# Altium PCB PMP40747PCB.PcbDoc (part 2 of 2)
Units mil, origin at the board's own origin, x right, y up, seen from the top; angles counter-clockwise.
Board outline 2952.76 x 3937.01 mil, 2 copper layers (Top Layer, Bottom Layer), stack 62 mil thick; 109 components, 53 nets, 257 pads, 138 vias.
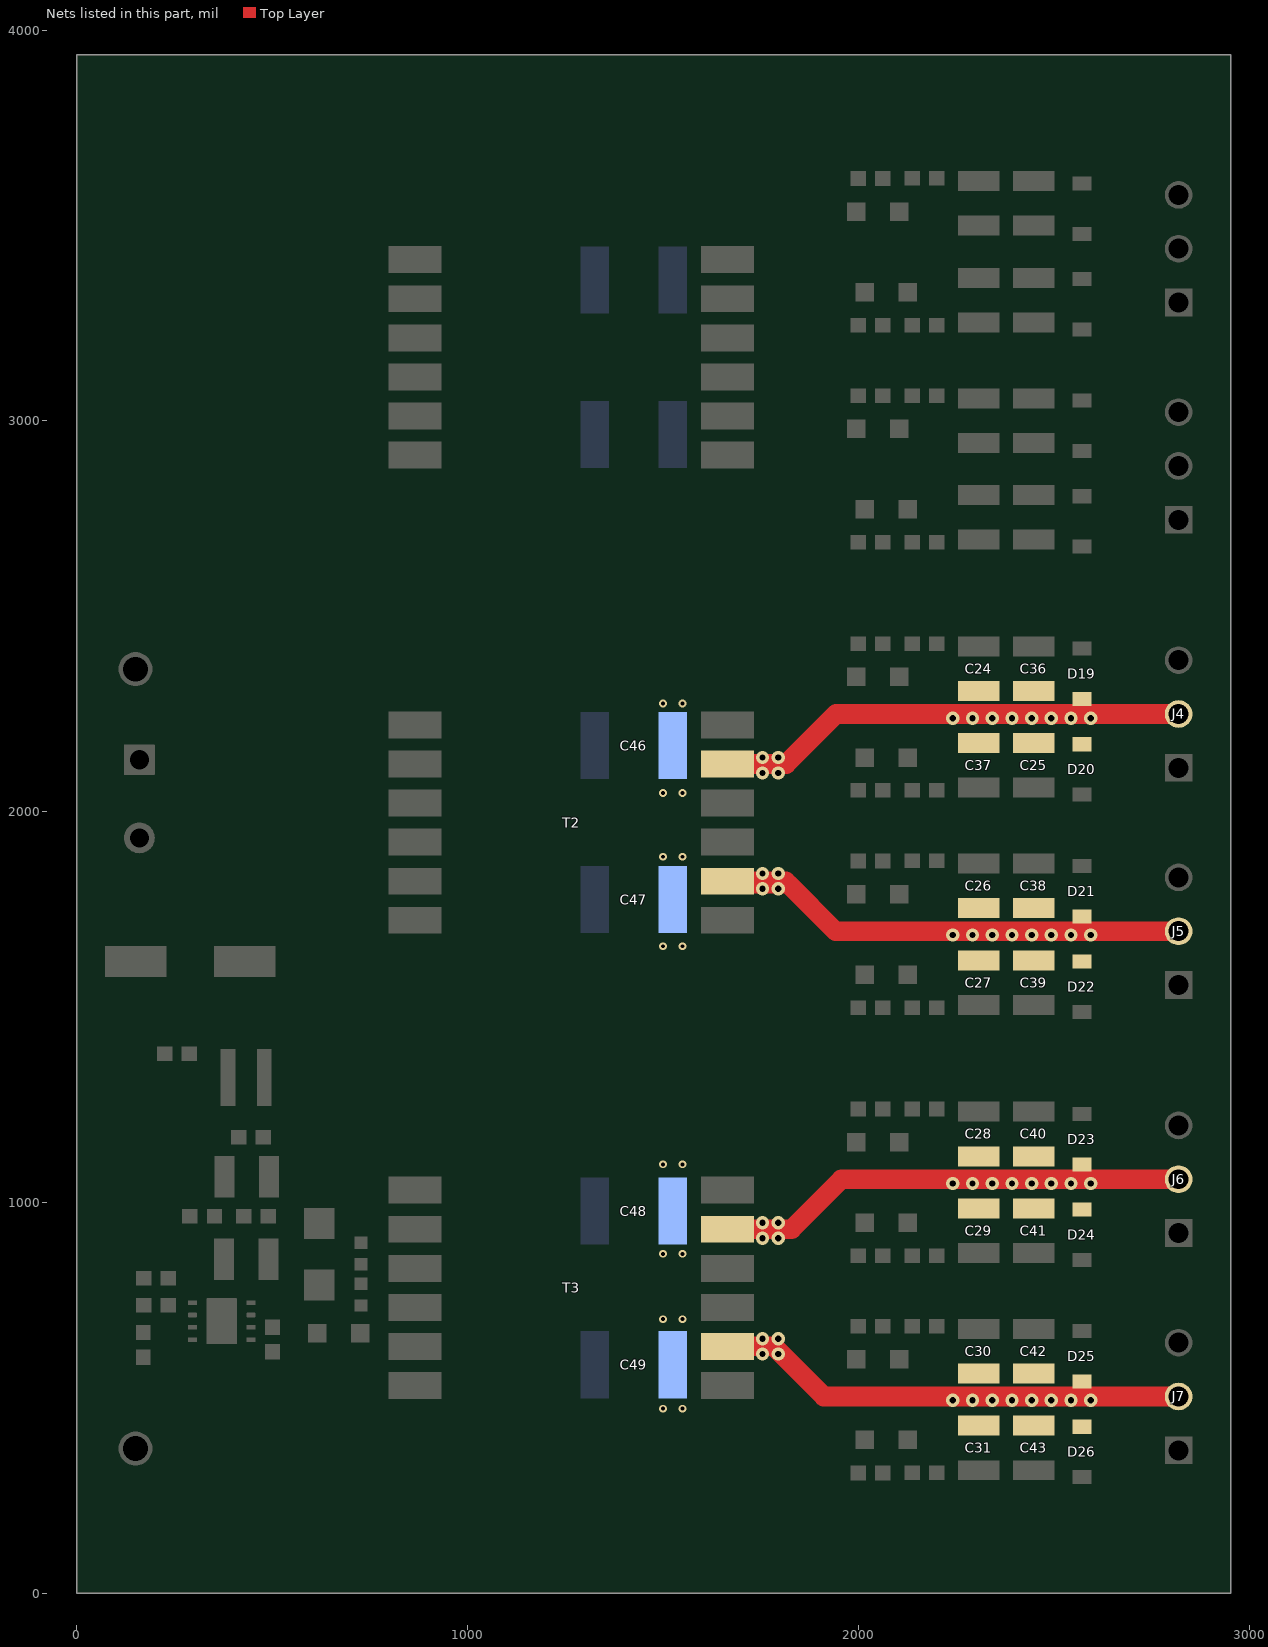
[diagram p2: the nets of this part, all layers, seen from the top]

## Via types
v1: diameter 34, hole 16, Top Layer to Bottom Layer, tented both sides, 72 vias
v2: diameter 20, hole 10, Top Layer to Bottom Layer, tented both sides, 48 vias
v3: diameter 30, hole 15, Top Layer to Bottom Layer, tented both sides, 10 vias
v4: diameter 196.85, hole 118.11, Top Layer to Bottom Layer, 4 vias
v5: diameter 19.68, hole 7.87, Top Layer to Bottom Layer, 4 vias

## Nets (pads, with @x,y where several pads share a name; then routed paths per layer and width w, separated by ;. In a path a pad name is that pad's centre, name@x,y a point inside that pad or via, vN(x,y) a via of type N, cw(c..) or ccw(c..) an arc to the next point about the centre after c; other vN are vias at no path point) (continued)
RTN_3: C24.1 C25.1 C36.1 C37.1 C46.1 D19.2 D20.1 J4.2 T2.11 | length 1207.8
  Top Layer w50: T2.11@1665,2122.06 1815.37,2122.06 1943.39,2250.07 J4.2@2819.77,2250.07
  other v1: 1755,2099.19 1795,2099.19 1755,2138.64 1795,2138.64 2241.82,2239.19 2292.27,2239.19 2342.73,2239.19 2393.18,2239.19 2443.64,2239.19 2494.09,2239.19 2544.55,2239.19 2595,2239.19
  other v2: 1500,2048.12 1550,2048.12 1500,2277.17 1550,2277.17
RTN_4: C26.1 C27.1 C38.1 C39.1 C47.1 D21.2 D22.1 J5.2 T2.8 | length 1356.6
  Top Layer w50: 1813.77,1822.06 T2.8@1665,1822.06 1671.03,1816.03 1819.8,1816.03 1941.79,1694.04 J5.2@2819.77,1694.04
  other v1: 2241.82,1684.19 2292.27,1684.19 2342.73,1684.19 2393.18,1684.19 2443.64,1684.19 2494.09,1684.19 2544.55,1684.19 2595,1684.19 1754.96,1802.6 1794.96,1802.6 1754.96,1842.06 1794.96,1842.06
  other v2: 1500,1655.62 1550,1655.62 1500,1884.67 1550,1884.67
RTN_5: C28.1 C29.1 C40.1 C41.1 C48.1 D23.2 D24.1 J6.2 T3.11 | length 1207.8
  Top Layer w50: T3.11@1665,931.24 1828.98,931.24 1957,1059.26 J6.2@2819.77,1059.26
  other v1: 1755,908.37 1795,908.37 1755,947.82 1795,947.82 2241.82,1048.37 2292.27,1048.37 2342.73,1048.37 2393.18,1048.37 2443.64,1048.37 2494.09,1048.37 2544.55,1048.37 2595,1048.37
  other v2: 1500,868.37 1550,868.37 1500,1097.42 1550,1097.42
RTN_6: C30.1 C31.1 C42.1 C43.1 C49.1 D25.2 D26.1 J7.2 T3.8 | length 1207.8
  Top Layer w50: T3.8@1665,631.24 1783.86,631.24 1911.88,503.22 J7.2@2819.77,503.22
  other v1: 2241.82,493.37 2292.27,493.37 2342.73,493.37 2393.18,493.37 2443.64,493.37 2494.09,493.37 2544.55,493.37 2595,493.37 1754.96,611.79 1794.96,611.79 1754.96,651.24 1794.96,651.24
  other v2: 1500,472.03 1550,472.03 1500,701.08 1550,701.08
pads on no net: U1.9@370.73,666.35 U1.9@370.73,725.8
copper on no net:
  other v4: 196.85,118.11 2804.96,118.11 196.85,3818.9 2804.96,3818.9

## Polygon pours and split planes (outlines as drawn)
GND on Top Layer "TOP_LAYER_GND_P154" (solid, remove dead copper, pour order 154): 0,3937.01 1362,3937.01 1362,0 0,0
no net on Top Layer "TOP_LAYER_NONET_P140" (solid, remove dead copper, pour order 140): 1600,1069.55
+15V_5 on Top Layer "TOP_LAYER_+15V_5_P138" (solid, remove dead copper, pour order 138): 2174.04,1261.78 2190.64,1278.37 2865,1278.37 2882.76,1260.61 2882.76,1177.18 2863.96,1158.37 2202,1158.37 2174.04,1186.33
RTN_5 on Top Layer "TOP_LAYER_RTN_5_P136" (solid, remove dead copper, pour order 136): 2866,978.37 2878,990.37 2878,1126.37 2861,1143.37 2218,1143.37 2173,1098.37 1899,1098.37 1769,968.37 1596,968.37 1596,888.37 1849,888.37 1957,996.37 2185,996.37 2233,948.37 2746,948.37 2776,978.37
-8V_5 on Top Layer "TOP_LAYER_-8V_5_P134" (solid, remove dead copper, pour order 134): 2865,834.37 2878,847.37 2878,950.37 2865,963.37 2783,963.37 2753,933.37 2204,933.37 2178.43,907.8 2178.43,846.95 2191,834.37
NetD12_1 on Top Layer "TOP_LAYER_NETD12_1_P132" (solid, remove dead copper, pour order 132): 1596,796.37 1596,865.37 1863,865.37 1970,972.37 2040,972.37 2040,911.13 2021,892.13 2021,844.37 1973,796.37
no net on Top Layer "TOP_LAYER_NONET_P130" (solid, remove dead copper, pour order 130): 1596,796.37
NetD11_2 on Top Layer "TOP_LAYER_NETD11_2_P128" (solid, remove dead copper, pour order 128): 1605.82,1075.37 1705,1075.37 1897.3,1267.67 2014,1267.67 2015.16,1267.67 2025,1257.82 2025,1127.37 2017,1119.37 1877.96,1119.37 1754.96,996.37 1597,996.37 1598.03,1067.58
no net on Top Layer "TOP_LAYER_NONET_P126" (solid, remove dead copper, pour order 126): 1597,996.37 1597,1064.37 1598,1065.37
-8V_6 on Top Layer "TOP_LAYER_-8V_6_P124" (solid, remove dead copper, pour order 124): 2865,278.33 2878,291.33 2878,394.33 2865,407.33 2783,407.33 2753,377.33 2204,377.33 2178.43,351.76 2178.43,290.91 2191,278.33
RTN_6 on Top Layer "TOP_LAYER_RTN_6_P122" (solid, remove dead copper, pour order 122): 1973.04,542.33 1847,668.37 1596,668.37 1596,592.37 1775,592.37 1927.04,440.33 2186.04,440.33 2234.04,392.33 2746,392.33 2776,422.33 2866,422.33 2878,434.33 2878,570.33 2861,587.33 2226.39,587.33 2181.39,542.33
+15V_6 on Top Layer "TOP_LAYER_+15V_6_P120" (solid, remove dead copper, pour order 120): 2178,709.7 2190.64,722.33 2865,722.33 2882.76,704.57 2882.76,621.14 2863.96,602.33 2202,602.33 2178,626.33
NetD14_1 on Top Layer "TOP_LAYER_NETD14_1_P118" (solid, remove dead copper, pour order 118): 2041,418.37 2047,412.37 2047,365.37 2025,343.37 2025,278.33 1915.04,278.33 1706.25,487.12 1605.82,487.12 1598.03,494.91 1597,566.12 1756.46,566.12 1904.21,418.37
NetD13_2 on Top Layer "TOP_LAYER_NETD13_2_P116" (solid, remove dead copper, pour order 116): 1596,766.12 1596,697.12 1851.31,697.12 1976.05,572.37 2024,572.37 2024,715.12 1973,766.12
no net on Top Layer "TOP_LAYER_NONET_P088" (solid, remove dead copper, pour order 88): 1600,2260.37
+15V_3 on Top Layer "TOP_LAYER_+15V_3_P086" (solid, remove dead copper, pour order 86): 2174.04,2452.59 2190.64,2469.19 2865,2469.19 2882.76,2451.42 2882.76,2367.99 2863.96,2349.19 2202,2349.19 2174.04,2377.14
RTN_3 on Top Layer "TOP_LAYER_RTN_3_P084" (solid, remove dead copper, pour order 84): 2866,2169.19 2878,2181.18 2878,2317.18 2861,2334.18 2218,2334.19 2173,2289.18 1899,2289.18 1769,2159.19 1596,2159.19 1596,2079.18 1849,2079.19 1957,2187.19 2185,2187.18 2233,2139.19 2746,2139.18 2776,2169.19
-8V_3 on Top Layer "TOP_LAYER_-8V_3_P082" (solid, remove dead copper, pour order 82): 2865,2025.19 2878,2038.18 2878,2141.19 2865,2154.18 2783,2154.18 2753,2124.18 2204,2124.19 2178.43,2098.61 2178.43,2037.76 2191,2025.19
NetD8_1 on Top Layer "TOP_LAYER_NETD8_1_P080" (solid, remove dead copper, pour order 80): 1596,1987.19 1596,2056.19 1863,2056.19 1970,2163.19 2040,2163.19 2040,2101.94 2021,2082.94 2021,2035.19 1973,1987.19
no net on Top Layer "TOP_LAYER_NONET_P078" (solid, remove dead copper, pour order 78): 1596,1987.19
NetD7_2 on Top Layer "TOP_LAYER_NETD7_2_P076" (solid, remove dead copper, pour order 76): 1605.82,2266.19 1705,2266.19 1897.3,2458.48 2014,2458.48 2015.16,2458.48 2025,2448.64 2025,2318.19 2017,2310.19 1877.96,2310.18 1754.96,2187.18 1597,2187.19 1598.03,2258.4
no net on Top Layer "TOP_LAYER_NONET_P074" (solid, remove dead copper, pour order 74): 1597,2187.19 1597,2255.19 1598,2256.19
-8V_4 on Top Layer "TOP_LAYER_-8V_4_P072" (solid, remove dead copper, pour order 72): 2865,1469.15 2878,1482.15 2878,1585.15 2865,1598.15 2783,1598.15 2753,1568.15 2204,1568.15 2178.43,1542.57 2178.43,1481.72 2191,1469.15
RTN_4 on Top Layer "TOP_LAYER_RTN_4_P070" (solid, remove dead copper, pour order 70): 1973.04,1733.15 1847,1859.19 1596,1859.18 1596,1783.19 1775,1783.19 1927.04,1631.15 2186.04,1631.15 2234.04,1583.15 2746,1583.15 2776,1613.15 2866,1613.15 2878,1625.15 2878,1761.15 2861,1778.15 2226.39,1778.15 2181.39,1733.15
+15V_4 on Top Layer "TOP_LAYER_+15V_4_P068" (solid, remove dead copper, pour order 68): 2178,1900.51 2190.64,1913.15 2865,1913.15 2882.76,1895.38 2882.76,1811.95 2863.96,1793.15 2202,1793.15 2178,1817.15
NetD10_1 on Top Layer "TOP_LAYER_NETD10_1_P066" (solid, remove dead copper, pour order 66): 2041,1609.19 2047,1603.18 2047,1556.19 2025,1534.19 2025,1469.15 1915.04,1469.15 1706.25,1677.93 1605.82,1677.93 1598.03,1685.72 1597,1756.93 1756.46,1756.93 1904.21,1609.19
NetD9_2 on Top Layer "TOP_LAYER_NETD9_2_P064" (solid, remove dead copper, pour order 64): 1596,1956.93 1596,1887.93 1851.31,1887.93 1976.05,1763.19 2024,1763.19 2024,1905.93 1973,1956.93
NetD5_2 on Top Layer "TOP_LAYER_NETD5_2_P062" (solid, remove dead copper, pour order 62): 1596,3147.75 1596,3078.75 1851.31,3078.75 1976.05,2954 2024,2954 2024,3096.75 1973,3147.75
NetD6_1 on Top Layer "TOP_LAYER_NETD6_1_P060" (solid, remove dead copper, pour order 60): 2041,2800 2047,2794 2047,2747 2025,2725 2025,2659.96 1915.04,2659.96 1706.25,2868.75 1605.82,2868.75 1598.03,2876.53 1597,2947.75 1756.46,2947.75 1904.21,2800
+15V_2 on Top Layer "TOP_LAYER_+15V_2_P058" (solid, remove dead copper, pour order 58): 2178,3091.33 2190.64,3103.96 2865,3103.96 2882.76,3086.2 2882.76,3002.77 2863.96,2983.96 2202,2983.96 2178,3007.96
RTN_2 on Top Layer "TOP_LAYER_RTN_2_P056" (solid, remove dead copper, pour order 56): 1973.04,2923.96 1847,3050 1596,3050 1596,2974 1775,2974 1927.04,2821.96 2186.04,2821.96 2234.04,2773.96 2746,2773.96 2776,2803.96 2866,2803.96 2878,2815.96 2878,2951.96 2861,2968.96 2226.39,2968.96 2181.39,2923.96
-8V_2 on Top Layer "TOP_LAYER_-8V_2_P054" (solid, remove dead copper, pour order 54): 2865,2659.96 2878,2672.96 2878,2775.96 2865,2788.96 2783,2788.96 2753,2758.96 2204,2758.96 2178.43,2733.39 2178.43,2672.54 2191,2659.96
no net on Top Layer "TOP_LAYER_NONET_P048" (solid, remove dead copper, pour order 48): 1597,3378 1597,3446 1598,3447
NetD3_2 on Top Layer "TOP_LAYER_NETD3_2_P046" (solid, remove dead copper, pour order 46): 1605.82,3457 1705,3457 1897.3,3649.3 2014,3649.3 2015.16,3649.3 2025,3639.45 2025,3509 2017,3501 1877.96,3501 1754.96,3378 1597,3378 1598.03,3449.21
no net on Top Layer "TOP_LAYER_NONET_P044" (solid, remove dead copper, pour order 44): 1596,3178
NetD4_1 on Top Layer "TOP_LAYER_NETD4_1_P042" (solid, remove dead copper, pour order 42): 1596,3178 1596,3247 1863,3247 1970,3354 2040,3354 2040,3292.75 2021,3273.75 2021,3226 1973,3178
-8V_1 on Top Layer "TOP_LAYER_-8V_1_P040" (solid, remove dead copper, pour order 40): 2865,3216 2878,3229 2878,3332 2865,3345 2783,3345 2753,3315 2204,3315 2178.43,3289.43 2178.43,3228.57 2191,3216
RTN_1 on Top Layer "TOP_LAYER_RTN_1_P038" (solid, remove dead copper, pour order 38): 2866,3360 2878,3372 2878,3508 2861,3525 2218,3525 2173,3480 1899,3480 1769,3350 1596,3350 1596,3270 1849,3270 1957,3378 2185,3378 2233,3330 2746,3330 2776,3360
+15V_1 on Top Layer "TOP_LAYER_+15V_1_P036" (solid, remove dead copper, pour order 36): 2174.04,3643.41 2190.64,3660 2865,3660 2882.76,3642.24 2882.76,3558.81 2863.96,3540 2202,3540 2174.04,3567.96
no net on Top Layer "TOP_LAYER_NONET_P034" (solid, remove dead copper, pour order 34): 1600,3451.18
NetC1_1 on Top Layer "TOP_LAYER_NETC1_1_P014" (solid, remove dead copper, pour order 14): 396.34,1220 420,1243.66 420,1427.6 551.19,1558.79 551.19,2148.73 471.85,2228.07 120,2228.07 100,2208.07 100,2071.67 117.28,2054.4 210.7,2054.4 265.59,1999.51 265.59,1273.19 318.78,1220
NetC3_1 on Top Layer "TOP_LAYER_NETC3_1_P006" (solid, remove dead copper, pour order 6): 602.04,882.09 519.95,800 461.42,800 458.23,803.19 458.23,1416.62 580,1538.38 580,3315.12 714.09,3449.21 934.87,3449.21 961.2,3422.88 961.2,3168 790,3168 790,2863 932,2863 948,2847 948,797.14 781.4,797.14 781.4,839.61 781.4,860.7 760,882.09
NetC6_2 on Top Layer "TOP_LAYER_NETC6_2_P012" (solid, remove dead copper, pour order 12): 790,786.06 754.57,750.63 702.89,750.63 690,737.74 690,600 817.53,472.47 901.1,472.47 1021.72,472.35 1117,567.63 1117,3049 1014,3152 790,3152
no net on Top Layer "TOP_LAYER_NONET_P000" (solid, remove dead copper, pour order 0): 6577.09,1430
GND on Bottom Layer "BOTTOM_LAYER_GND_P156" (solid, remove dead copper, pour order 156): 0,3937.01 1362,3937.01 1362,0 0,0
RTN_5 on Bottom Layer "BOTTOM_LAYER_RTN_5_P152" (solid, remove dead copper, pour order 152): 1480,1232.37 1515.08,1267.45 2930.01,1267.45 2930.01,794.16 1480,794.16
RTN_6 on Bottom Layer "BOTTOM_LAYER_RTN_6_P150" (solid, remove dead copper, pour order 150): 1480,326.37 1527.37,279 2181.35,279 2930.01,279 2930.01,765.92 1480,765.92
RTN_3 on Bottom Layer "BOTTOM_LAYER_RTN_3_P148" (solid, remove dead copper, pour order 148): 1480,2423.19 1515.08,2458.27 2930.01,2458.27 2930.01,1984.97 1480,1984.97
RTN_4 on Bottom Layer "BOTTOM_LAYER_RTN_4_P146" (solid, remove dead copper, pour order 146): 1480,1517.19 1527.37,1469.82 2181.35,1469.82 2930.01,1469.82 2930.01,1956.73 1480,1956.73
RTN_2 on Bottom Layer "BOTTOM_LAYER_RTN_2_P022" (solid, remove dead copper, pour order 22): 1480,2708 1527.37,2660.63 2181.35,2660.63 2930.01,2660.63 2930.01,3147.55 1480,3147.54
RTN_1 on Bottom Layer "BOTTOM_LAYER_RTN_1_P020" (solid, remove dead copper, pour order 20): 1480,3614 1515.08,3649.08 2930.01,3649.08 2930.01,3175.79 1480,3175.79

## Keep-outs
Keep-Out Layer:
  text ".Layer_Name" at 577,-858.49 h60

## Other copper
Top Layer:
  pour cut-out: 429.62,1205.87 446.93,1188.56 451.44,1193.06 451.44,1222.42 447.5,1226.36 416,1226.36 402.2,1205.87
  text ".Layer_Name" at 577,-858.49 h60
Bottom Layer:
  text ".Layer_Name" at 577,-858.49 h60

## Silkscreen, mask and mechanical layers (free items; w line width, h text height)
Top Overlay:
  text "PMP40747E1" at 233.69,2560 h108.27
  text ".Layer_Name" at 577,-858.49 h60
Bottom Overlay:
  text ".Layer_Name" at 577,-858.49 h60
Top Paste:
  text ".Layer_Name" at 577,-858.49 h60
Bottom Paste:
  text ".Layer_Name" at 577,-858.49 h60
Top Solder:
  text ".Layer_Name" at 577,-858.49 h60
  text ".Layer_Name" at 577,-858.49 h60
Bottom Solder:
  text ".Layer_Name" at 577,-858.49 h60
Drill Guide:
  text ".Layer_Name" at 577,-858.49 h60
M1 Board Outline:
  the board outline again, w10
  text ".Layer_Name" at 577,-858.49 h60
M2 Board Dimensions:
  rectangle: 0,-275 125,-150
  rectangle: 125,-400 500,-275
  lines w7: 0,-275 1000,-275 ; 125,-400 125,-150 ; 250,-400 250,-150 ; 500,-400 500,-150 ; 750,-400 750,-150 ; 0,-400 1000,-400 1000,-150 0,-150 0,-400
  text ".Layer_Name" at 577,-858.49 h60
M3 3D STEP Top:
  text ".Layer_Name" at 577,-858.49 h60
M4 3D STEP Bottom:
  text ".Layer_Name" at 577,-858.49 h60
M5 Assembly Top:
  lines w10: -292,-930.17 6308,-930.17 ; -292,-726.83 6310,-726.83 ; -292,-523.5 -292,-1133.5 3713,-1133.5 6310,-1133.5 6310,-523.5 -291.5,-523.5 -291.5,-1133.5 1284,-1133.5 ; 2173,-1133.5 2173,-523.5 ; 3440,-726.83 3440,-523.5 ; 4280,-726.83 4280,-523.5 ; 4902,-1140 4902,-937.17
  text "COMPONENTS MARKED 'DNP' SHOULD NOT BE POPULATED." at 1153.5,-318.5 h60
  text "ASSEMBLY VARIANT:" at 1153,-434 h60
  text ".VariantName" at 2189,-434 h60
  text "PCB VIEWED FROM TOP SIDE" at -228.5,-655.67 h60
  text "BOARD #:" at 2248,-655.67 h60
  text ".PRJ_Number" at 2793.5,-655.67 h60
  text "REV:" at 3638,-655.67 h60
  text ".PCB_Rev" at 3929.5,-655.67 h60
  text "SVN REV:" at 4476,-655.67 h60
  text ".VersionControl_RevNumber" at 4982,-655.67 h60
  text "TID #:" at 2248,-859 h60
  text ".TID" at 2793.5,-859 h60
  text "PLOT NAME =" at -228.5,-1064.34 h60
  text ".plot_File_Name" at 577,-1064.34 h60
  text "GENERATED    :" at 2250,-1064.34 h60
  text ".Print_Date" at 3119.5,-1064.34 h60
  text ".Print_Time" at 3848.5,-1064.34 h60
  text "TEXAS INSTRUMENTS" at 5113,-1064.34 h60
M6 Assembly Bottom:
  lines w10: -292.5,-727.33 6309.5,-727.33 ; -290.5,-930.67 6309.5,-930.67 ; 1115.5,-1140.5 1115.5,-937.67 ; 1737.5,-727.33 1737.5,-524 ; 2577.5,-727.33 2577.5,-524 ; 3844.5,-1134 3844.5,-524 ; 4733.5,-1134 6309,-1134 6309,-524 -292.5,-524 -292.5,-1134 2304.5,-1134 6309.5,-1134 6309.5,-524
  text "COMPONENTS MARKED 'DNP' SHOULD NOT BE POPULATED." at 6102,-318 h60
  text ".VariantName" at 5058,-434 h60
  text "ASSEMBLY VARIANT:" at 6097,-434 h60
  text ".VersionControl_RevNumber" at 1035.5,-656.17 h60
  text "SVN REV:" at 1541.5,-656.17 h60
  text ".PCB_Rev" at 2088,-656.17 h60
  text "REV:" at 2379.5,-656.17 h60
  text ".PRJ_Number" at 3224,-656.17 h60
  text "BOARD #:" at 3769.5,-656.17 h60
  text "PCB VIEWED FROM BOTTOM SIDE" at 6246,-656.17 h60
  text ".TID" at 3224,-859.5 h60
  text "TID #:" at 3769.5,-859.5 h60
  text "TEXAS INSTRUMENTS" at 904.5,-1064.84 h60
  text ".Print_Time" at 2169,-1064.84 h60
  text ".Print_Date" at 2898,-1064.84 h60
  text "GENERATED    :" at 3767.5,-1064.84 h60
  text ".plot_File_Name" at 5440.5,-1064.84 h60
  text "PLOT NAME =" at 6246,-1064.84 h60
M9 Title Sheet:
  drawing of 57 lines, arcs and shapes, not listed
  text "1" at 739.84,8036.5 h70
  text "2" at 3235.5,8036.5 h70
  text "3" at 5724.84,8036.5 h70
  text "4" at 8231.51,8036.5 h70
  text "5" at 10730.5,8036.5 h70
  text "6" at 13235.5,8036.5 h70
  text "A" at -416.5,6893.5 h70
  text "A" at 14383.5,6893.5 h70
  text "B" at -416.5,4513.5 h70
  text "B" at 14383.5,4513.5 h70
  text "C" at -416.5,2138.5 h70
  text "C" at 14383.5,2138.5 h70
  text "PROJECT TITLE:" at 11343.5,277.5 h45
  text ".PRJ_Title" at 11393.5,144.17 h70
  text "DESIGNED FOR:" at 11343.5,-23.5 h45
  text ".PRJ_Customer" at 11393.5,-163.5 h70
  text "D" at -416.5,-231.5 h70
  text "D" at 14383.5,-231.5 h70
  text "FILE NAME:" at 11343.5,-323.5 h45
  text ".PCB_File_Name_No_Path" at 11393.5,-443.5 h70
  text "Texas Instruments (TI) and/or its licensors do not warrant the accuracy or completeness of this specification" at 6374,-605.34 h45
  text "ENGINEER:" at 11343.5,-613.5 h45
  text "LAYOUT BY:" at 12848.5,-613.5 h45
  text "or any information contained therein. TI and/or its licensors do not warrant that this design will meet" at 6329.01,-718 h45
  text ".PRJ_Engineer" at 11393.5,-768.49 h70
  text ".PCB_Layout" at 12899,-768.49 h70
  text "the specifications, will be suitable for your application or fit for any particular purpose, or will operate in" at 6329.01,-830.67 h45
  text ".Layer_Name" at 577,-858.49 h60
  text "ALTIUM DESIGNER VERSION:" at 12848.5,-923.5 h45
  text "an implementation. TI and/or its licensors do not warrant that the design is production worthy. You should" at 6329.01,-943.33 h45
  text "completely validate and test your design implementation to confirm the system functionality for your application." at 6374,-1056 h45
  text ".print_Scale" at 11393.5,-1056.83 h70
  text ".Application_BuildNumber" at 12899,-1056.83 h70
  text "1" at 739.84,-1263.5 h70
  text "2" at 3235.5,-1263.5 h70
  text "3" at 5724.84,-1263.5 h70
  text "4" at 8231.51,-1263.5 h70
  text "5" at 10730.5,-1263.5 h70
  text "6" at 13235.5,-1263.5 h70
M10 Fab Notes:
  drawing of 189 lines, arcs and shapes, not listed
  text "DESIGN INFORMATION" at 12382.02,6356.17 h60
  text "MIN. TRACK WIDTH:" at 11737.46,6224.05 h60
  text "8" at 12833.7,6224.05 h60
  text "MIL" at 12988.46,6224.05 h60
  text "MIN. CLEARANCE:" at 11737.46,6099.92 h60
  text "0.2" at 12773.7,6099.93 h60
  text "mm" at 12988.46,6099.92 h60
  text "MIN. VIA PAD SIZE:" at 11737.46,5975.8 h60
  text "24" at 12803.71,5975.8 h60
  text "MIL" at 12988.46,5975.8 h60
  text "0.05mm (2MIL)" at 12432.46,5845.9 h60
  text "MINIMUM ANNULAR RING" at 11408.23,5837.67 h60
  text "EXTERNAL" at 13140.46,5837.67 h60
  text "PER" at 11608.23,5727.55 h60
  text "IPC-D-275 CLASS 2 LEVEL C" at 11828.23,5727.54 h60
  text "MIL, HOLES" at 13316.46,5627.07 h60
  text "+/-" at 12924,5618.48 h60
  text "+/-" at 13778,5618.48 h60
  text "REGISTRATION TOLERANCES:" at 11408.23,5617.42 h60
  text "METAL" at 12608,5617.42 h60
  text "5" at 13184.2,5617.42 h60
  text "3" at 14017.2,5617.42 h60
  text "MIL" at 14133.46,5617.42 h60
  text "HOLE SIZE TOLERANCE (UNLESS OTHERWISE SPECIFIED):" at 11408.23,5519.1 h60
  text "+/-" at 13778,5516.23 h60
  text "3" at 14017.2,5515.17 h60
  text "MIL" at 14133.46,5515.17 h60
  text "MATERIAL:" at 11333.46,5377.52 h60
  text "FR-4 High Tg" at 12319.9,5249 h60
  text "X" at 12175.46,5241.01 h60
  text "FR-408" at 11754.46,5236.49 h60
  text "OTHER" at 13242.46,5236.49 h60
  text "62 MIL (1.6mm) +/-10%" at 12074.56,5093.46 h60
  text "X" at 11954.46,5091.01 h60
  text "THICKNESS:" at 11408.23,5085.24 h60
  text "OTHER" at 13359.46,5085.24 h60
  text "TOLERANCE:" at 11408.23,4946.92 h60
  text "X" at 12256.46,4946.92 h60
  text "ANSI IPC-6012 TYPE 3 CLASS 2" at 12434.48,4946.92 h60
  text "OTHER +/-" at 12434.46,4802.73 h60
  text "BOW & TWIST:" at 11408.23,4657.54 h60
  text "X" at 12256.46,4657.54 h60
  text "ANSI IPC-6012 TYPE 3 CLASS 2" at 12434.48,4657.54 h60
  text "OTHER +/-" at 12434.46,4510.85 h60
  text "DRILLING:" at 11333.46,4380.23 h60
  text "NC_DRILL FILES" at 13094.46,4275.04 h60
  text "REFERENCE:" at 11408.23,4271.1 h60
  text "X" at 12065.46,4271.01 h60
  text "AS SHOWN" at 12243.46,4271.1 h60
  text "X" at 12966.46,4271.1 h60
  text "OTHER" at 13392.46,4128.85 h60
  text "PTH COPPER THICKNESS:" at 11407.91,4125.32 h60
  text "X" at 12547.14,4125.32 h60
  text "20-30 um" at 12675.14,4125.32 h60
  text "BOARD FINISH:" at 11333.46,3977.73 h60
  text "SILKSCREEN:" at 11488.68,3867.6 h60
  text "X" at 12446.46,3867.6 h60
  text "TOP" at 12563.46,3867.6 h60
  text "X" at 12956.46,3867.6 h60
  text "BOTTOM" at 13074.46,3867.6 h60
  text "SILKSCREEN COLOR:" at 11488.68,3712.41 h60
  text "X" at 12445.46,3712.41 h60
  text "WHITE" at 12563.46,3712.41 h60
  text "OTHER" at 13074.46,3712.41 h60
  text "X" at 12576.46,3568.96 h60
  text "GREEN" at 12694.46,3568.96 h60
  text "OTHER" at 13312.46,3568.96 h60
  text "SOLDER RESIST COLOR:" at 11488.68,3562.1 h60
  text "X" at 12576.46,3414.71 h60
  text "MATTE" at 12694.46,3414.71 h60
  text "SEMI-GLOSS" at 13312,3414.07 h60
  text "IMMERSION GOLD (ENIG)" at 12394.46,3241.94 h60
  text "ENEPIG" at 13732,3234.72 h60
  text "SURFACE FINISH:" at 11333.46,3233.72 h60
  text "X" at 12216.46,3233.72 h60
  text "IMM. TIN/SILVER OR EQUIV" at 11663,3096.4 h60
  text "OTHER" at 13094.46,3092.47 h60
  text "ARRAY/PANEL:" at 11333.46,2937.09 h60
  text "CUT AND TRIM PER M1 BOARD OUTLINE" at 12394.46,2928.87 h60
  text "N.C. ROUTE" at 12394.46,2792.9 h60
  text "X" at 13082.46,2792.9 h60
  text "V. SCORE" at 13260.46,2792.9 h60
  text "CERTIFICATION:" at 11333.46,2663.77 h60
  text "MATERIALS AND WORKMANSHIP FOR ALL PCBS" at 12058.46,2663.77 h60
  text "TO MEET OR EXCEED THE REQUIREMENTS OF:" at 12058.46,2569.71 h60
  text "X" at 11695.97,2441.08 h60
  text "ANSI IPC-A-600F CLASS ->" at 11823.96,2441.08 h60
  text "X" at 13471.97,2441.08 h60
  text "2" at 13581.96,2441.08 h60
  text "1" at 13266.96,2439.58 h60
  text "3" at 13935.96,2439.58 h60
  text "X" at 12507.97,2293.39 h60
  text "RoHS" at 12635.96,2293.39 h60
  text "OTHER" at 13280.36,2293.39 h60
  text "PER ORDER" at 13677.42,2293.39 h60
  text "ALL BOARDS MUST MEET OR EXCEED UL94-V0 REQUIREMENTS." at 11361,2139.57 h60
  text "PCB MUST BEAR THE UL94V-0 UL REGISTERED MATERIAL ID NUMBER" at 11361,2023.5 h60
  text "ADDITIONAL REQUIREMENTS:" at 11333.46,1854.08 h60
  text "MICROSECTION:" at 11408.23,1746.95 h60
  text "YES" at 12313.96,1746.95 h60
  text "REQUIRED" at 13175.46,1602.62 h60
  text "BARE BOARD ELEC. TEST:" at 11408.23,1599.76 h60
  text "NONE" at 12713.96,1599.76 h60
  text "X" at 13057.46,1599.76 h60
  text "PER ORDER" at 13767.46,1599.76 h60
  text "XX MIL VIAS REQUIRE NON-CONDUCTIVE FILL AND PLANARIZE" at 11576.38,1394.82 h59
  text "XX MIL VIAS REQUIRE CONDUCTIVE FILL AND PLANARIZE" at 11584.38,1290.84 h60
  text "OUTER XX MIL TRACES REQUIRE 50 OHM SINGLE-ENDED IMPEDANCE" at 11583.39,1127.46 h58
  text "LAYER 2 & 3 (INNER LAYERS) XX MIL WIDE, XX MIL SPACE / TRACES REQUIRE 100 OHM DIFFERENTIAL IMPEDANCE" at 11575.39,891.74 h60
  text ".Layer_Name" at 577,-858.49 h60
M11 Gerber Information:
  lines w10: -292,-930.17 6308,-930.17 ; -292,-726.83 6310,-726.83 ; -292,-523.5 -292,-1133.5 3713,-1133.5 6310,-1133.5 6310,-523.5 -291.5,-523.5 -291.5,-1133.5 1284,-1133.5 ; 2173,-1133.5 2173,-523.5 ; 3440,-726.83 3440,-523.5 ; 4280,-726.83 4280,-523.5 ; 4902,-1140 4902,-937.17
  text "ALL ARTWORK VIEWED FROM TOP SIDE" at -228.5,-655.67 h60
  text "BOARD #:" at 2248,-655.67 h60
  text ".PRJ_Number" at 2793.5,-655.67 h60
  text "REV:" at 3638,-655.67 h60
  text ".PCB_Rev" at 3929.5,-655.67 h60
  text "SVN REV:" at 4476,-655.67 h60
  text ".VersionControl_RevNumber" at 4982,-655.67 h60
  text "LAYER NAME =" at -228.5,-858.49 h60
  text "TID #:" at 2248,-859 h60
  text ".TID" at 2793.5,-859 h60
  text "PLOT NAME =" at -228.5,-1064.34 h60
  text ".plot_File_Name" at 577,-1064.34 h60
  text "GENERATED    :" at 2250,-1064.34 h60
  text ".Print_Date" at 3119.5,-1064.34 h60
  text ".Print_Time" at 3848.5,-1064.34 h60
  text "TEXAS INSTRUMENTS" at 5113,-1064.34 h60
M12 Stackup:
  drawing of 191 lines, arcs and shapes, not listed
  text "Layer" at 9811.59,7469.94 h60
  text "Name" at 10221.51,7469.94 h60
  text "Material" at 11151.25,7469.94 h60
  text "Thickness" at 12011.02,7469.94 h60
  text "Constant" at 12660.85,7469.94 h60
  text "Board Layer Stack" at 13230.71,7469.94 h60
  text "1" at 9811.59,7349.94 h60
  text "Top Overlay" at 10221.51,7349.94 h60
  text "2" at 9811.59,7229.94 h60
  text "Top Solder" at 10221.51,7229.94 h60
  text "Solder Resist" at 11151.25,7229.94 h60
  text "0.40mil" at 12011.02,7229.94 h60
  text "3.5" at 12660.85,7229.94 h60
  text "3" at 9811.59,7109.94 h60
  text "Top Layer" at 10221.51,7109.94 h60
  text "Copper" at 11151.25,7109.94 h60
  text "1.40mil" at 12011.02,7109.94 h60
  text "4" at 9811.59,6989.94 h60
  text "Dielectric1" at 10221.51,6989.94 h60
  text "FR-4" at 11151.25,6989.94 h60
  text "59.20mil" at 12011.02,6989.94 h60
  text "4.8" at 12660.85,6989.94 h60
  text "5" at 9811.59,6869.94 h60
  text "Bottom Layer" at 10221.51,6869.94 h60
  text "Copper" at 11151.25,6869.94 h60
  text "1.40mil" at 12011.02,6869.94 h60
  text "6" at 9811.59,6749.94 h60
  text "Bottom Solder" at 10221.51,6749.94 h60
  text "Solder Resist" at 11151.25,6749.94 h60
  text "0.40mil" at 12011.02,6749.94 h60
  text "3.5" at 12660.85,6749.94 h60
  text "7" at 9811.59,6629.94 h60
  text "Bottom Overlay" at 10221.51,6629.94 h60
  text ".Layer_Name" at 577,-858.49 h60
M13 Component Bodies Top:
  text ".Layer_Name" at 577,-858.49 h60
M14 Component Bodies Bottom:
  text ".Layer_Name" at 577,-858.49 h60
M15 Courtyards Top:
  text ".Layer_Name" at 577,-858.49 h60
M16 Courtyards Bottom:
  text ".Layer_Name" at 577,-858.49 h60
Drill Drawing:
  circle w10: c5363.72,2528.04 r27.63
  lines w10: 5336.09,2638.55 5349.9,2638.55 5349.9,2624.74 5377.53,2624.74 5377.53,2638.55 5391.34,2638.55 5391.34,2666.18 5377.53,2666.18 5377.53,2679.99 5349.9,2679.99 5349.9,2666.18 5336.09,2666.18 5336.09,2638.55 ; 5336.09,2749.06 5391.34,2749.06 5391.34,2804.31 5336.09,2804.31 5336.09,2749.06 ; 5336.09,2887.19 5349.9,2887.19 5363.72,2873.38 5377.53,2887.19 5391.34,2887.19 5377.53,2901 5391.34,2914.82 5377.53,2914.82 5363.72,2928.63 5349.9,2914.82 5336.09,2914.82 5349.9,2901 5336.09,2887.19 ; 5336.09,3052.95 5391.34,3052.95 5363.72,2997.7 5336.09,3052.95 ; 5336.09,3122.02 5336.09,3135.83 5349.9,3149.64 5336.09,3163.46 5336.09,3177.27 5349.9,3177.27 5363.72,3163.46 5377.53,3177.27 5391.34,3177.27 5391.34,3163.46 5377.53,3149.64 5391.34,3135.83 5391.34,3122.02 5377.53,3122.02 5363.72,3135.83 5349.9,3122.02 5336.09,3122.02 ; 5336.09,3273.96 5363.72,3246.34 5391.34,3273.96 5363.72,3301.59 5336.09,3273.96 ; 5336.09,3370.66 5363.72,3384.47 5391.34,3370.66 5377.53,3398.28 5391.34,3425.91 5363.72,3412.1 5336.09,3425.91 5349.9,3398.28 5336.09,3370.66
  lines w12: 5286,2463.12 8517.49,2463.12 ; 5286,3457.68 8517.49,3457.68 ; 5623.86,2338.8 5623.86,3582 ; 5955.86,2338.8 5955.86,3582 ; 6592.43,2338.8 6592.43,3582 ; 6851.57,2338.8 6851.57,3582 ; 7226.72,2338.8 7226.72,3582 ; 7951.05,2338.8 7951.05,3582 ; 5286,2338.8 8517.49,2338.8 8517.49,3582 5286,3582 5286,2338.8
  text "Symbol" at 5360.59,3494.98 h72
  text "Quantity" at 5661.16,3494.98 h72
  text "Finished Hole Size" at 5993.16,3494.98 h72
  text "Plated" at 6629.72,3494.98 h72
  text "Hole Type" at 6888.86,3494.98 h72
  text "Drill Layer Pair" at 7264.02,3494.98 h72
  text "Hole Tolerance" at 7988.35,3494.98 h72
  text "4" at 5661.16,3370.66 h60
  text "7.87mil (0.200mm)" at 5993.16,3370.66 h60
  text "PTH" at 6629.72,3370.66 h60
  text "Round" at 6888.86,3370.66 h60
  text "Top Layer - Bottom Layer" at 7264.02,3370.66 h60
  text "48" at 5661.16,3246.34 h60
  text "10.00mil (0.254mm)" at 5993.16,3246.34 h60
  text "PTH" at 6629.72,3246.34 h60
  text "Round" at 6888.86,3246.34 h60
  text "Top Layer - Bottom Layer" at 7264.02,3246.34 h60
  text "10" at 5661.16,3122.02 h60
  text "15.00mil (0.381mm)" at 5993.16,3122.02 h60
  text "PTH" at 6629.72,3122.02 h60
  text "Round" at 6888.86,3122.02 h60
  text "Top Layer - Bottom Layer" at 7264.02,3122.02 h60
  text "72" at 5661.16,2997.7 h60
  text "16.00mil (0.406mm)" at 5993.16,2997.7 h60
  text "PTH" at 6629.72,2997.7 h60
  text "Round" at 6888.86,2997.7 h60
  text "Top Layer - Bottom Layer" at 7264.02,2997.7 h60
  text "2" at 5661.16,2873.38 h60
  text "49.21mil (1.250mm)" at 5993.16,2873.38 h60
  text "PTH" at 6629.72,2873.38 h60
  text "Round" at 6888.86,2873.38 h60
  text "Top Layer - Bottom Layer" at 7264.02,2873.38 h60
  text "18" at 5661.16,2749.06 h60
  text "51.18mil (1.300mm)" at 5993.16,2749.06 h60
  text "PTH" at 6629.72,2749.06 h60
  text "Round" at 6888.86,2749.06 h60
  text "Top Layer - Bottom Layer" at 7264.02,2749.06 h60
  text "2" at 5661.16,2624.74 h60
  text "63.00mil (1.600mm)" at 5993.16,2624.74 h60
  text "PTH" at 6629.72,2624.74 h60
  text "Round" at 6888.86,2624.74 h60
  text "Top Layer - Bottom Layer" at 7264.02,2624.74 h60
  text "4" at 5661.16,2500.42 h60
  text "118.11mil (3.000mm)" at 5993.16,2500.42 h60
  text "PTH" at 6629.72,2500.42 h60
  text "Round" at 6888.86,2500.42 h60
  text "Top Layer - Bottom Layer" at 7264.02,2500.42 h60
  text "160 Total" at 5661.16,2376.1 h60
  text ".Layer_Name" at 577,-858.49 h60
M17 Embedded Cavity:
  text ".Layer_Name" at 577,-858.49 h60
M18 Embedded Assembly:
  text ".Layer_Name" at 577,-858.49 h60
M19 Embedded Keepout:
  text ".Layer_Name" at 577,-858.49 h60

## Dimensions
0,0 to 0,3937.01 on M2 Board Dimensions
0,0 to 2952.76,0 on M2 Board Dimensions
0,-400 to 1000,-400 on M2 Board Dimensions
